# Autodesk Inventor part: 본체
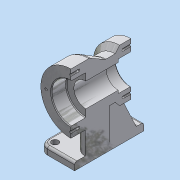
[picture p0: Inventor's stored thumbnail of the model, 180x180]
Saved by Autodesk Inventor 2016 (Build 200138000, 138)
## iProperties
Created: 2019-01
Part Number: 본체
Material: 알루미늄 6061
Document SubType Name: Modeling
Designer: Administrator
Density: 2.7 g/cm^3
Appearance: 알루미늄 - 평지
Mass: 897.041 g
Surface Area: 614.897 cm^2
Volume: 332.237 cm^3
Author: Administrator
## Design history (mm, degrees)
sketch "스케치1"
  geometry: L1 (46, -46)-(-46, -46); L2 (-46, -46)-(-46, 46); L3 (-46, 46)-(46, 46); L4 (46, 46)-(46, -46); L5 (46, -46)-(-46, 46); L6 (-46, -46)-(46, 46); 1 further point
  constraints: 12 end point, 2 midpoint, 2 parallel, 1 horizontal, 1 perpendicular
  dimensions: "d0" = 92 distance of L2.end L3.end; "d1" = 92 distance of L1.end L2.end
extrude "돌출1" new body sketch "스케치1" distance "d2" = 10; taper "d3" = 0 deg
fillet "모깎기1" dims "d4" = 10
sketch "스케치2"
  geometry: L1 (-46, 0)-(-51, 0); L2 (-51, 0)-(-51, 80); L3 (-86.37, 80)-(85.306, 80); L4 (-51, 80)-(-51, 120); L5 (-51, 120)-(-26, 120); L6 (-26, 120)-(-5.215, 108); L7 (-5.215, 108)-(8.126, 108); L8 (8.126, 108)-(14, 115); L9 (14, 115)-(29, 115); L10 (29, 115)-(29, 80); L11 (-51, 80)-(29, 80); 1 further point
  constraints: 22 end point, 3 perpendicular, 2 horizontal, 2 parallel, 1 collinear, 1 point on line, 1 vertical
  dimensions: "d5" = 5 distance of L1.start L1.end; "d6" = 80 distance of L1.end L2.end; "d7" = 40 distance of L2.end L4.end; "d8" = 25 distance of L4.end L5.end; "d9" = 30 deg angle of L7 L6; "d10" = 50 deg angle of L7 L8; "d11" = 15 distance of L8.end L9.end; "d12" = 80 horizontal distance of L9.end L4.end; "d13" = 70 diameter of L9 L3; "d14" = 56 diameter of L7 L3
revolve "회전1" sketch "스케치2" stored, may be unused: angle "d15" = 90 deg
sketch "스케치3"
  geometry: L1 (-51, 40)-(-51, 120) reference; L2 (-69.608, 80)-(66.232, 80); L3 (-51, 80)-(-51, 106); L4 (-51, 106)-(-31, 106); L5 (-31, 106)-(-31, 96); L6 (-31, 96)-(12, 96); L7 (12, 96)-(12, 100); L8 (12, 100)-(29, 100); L9 (29, 45)-(29, 115) reference; L10 (29, 100)-(29, 80); L11 (-51, 80)-(29, 80); 1 further point
  constraints: 18 end point, 5 perpendicular, 3 point on line, 2 horizontal, 2 midpoint
  dimensions: "d17" = 20 distance of L3.end L4.end; "d18" = 17 distance of L7.end L8.end; "d20" = 32 diameter of L6 L2; "d21" = 40 diameter of L8 L2; "d22" = 52 diameter of L4 L2
revolve "회전2" sketch "스케치3" stored, may be unused: angle "d23" = 90 deg
sketch "스케치5"
  geometry: L1 (-36, 46)-(36, 46) reference; L2 (46, 36)-(46, -36) reference; L3 (36, -46)-(-36, -46) reference; L4 (-46, -36)-(-46, 36) reference; C1 r 4.5 at (-36, 36); C2 r 4.5 at (36, 36); C3 r 4.5 at (-36, -36); C4 r 4.5 at (36, -36); A1 r 10 centre (-36, 36) between (-36, 46) and (-46, 36) reference; A2 r 10 centre (36, 36) between (46, 36) and (36, 46) reference; A3 r 10 centre (36, -36) between (36, -46) and (46, -36) reference; A4 r 10 centre (-36, -36) between (-46, -36) and (-36, -46) reference; 1 further point
  constraints: 4 centre point, 4 coincident
  dimensions: "d25" = 9 diameter of C1; "d26" = 9 diameter of C2; "d27" = 9 diameter of C3; "d28" = 9 diameter of C4
extrude "돌출2" cut sketch "스케치5" stored distance "d29" = 10; taper "d30" = 0 deg
sketch "스케치6"
  geometry: L1 (0, 72)-(0, 0) reference; L2 (-10, -10)-(0, -10) reference; 2 further points
  constraints: 1 other
  dimensions: "d31" = 4 distance from line of L1 point (-4, 36); "d32" = 46 distance from line of L2 point (-4, 36)
feature "엠보싱1" sketch "스케치6" dims "d0" = 92, "d1" = 92, "d33" = 0.5, "d34" = 0
fillet "모깎기2" dims "d35" = 3
sketch "스케치8" dims "d37" = 66
  geometry: L1 (0, 0)-(0, 33); C1 r 26 at (0, 0) reference; C2 r 40 at (0, 0) reference; C3 r 26 at (0, 0) reference; C4 r 16 at (0, 0) reference; 1 further point
  constraints: 2 end point, 1 coincident, 1 vertical, 1 vertical alignment, 2 other
hole "구멍1" sketch "스케치8" at (0, 33) diameter "d38" = 3.242; stored, may be unused: countersink angle "d42" = 82 deg, drill point angle "d44" = 118 deg; dims "d39" = 9, "d40" = 3.023, "d41" = 2, "d43" = 11
sketch "스케치9" dims "d48" = 55
  geometry: L1 (0, 0)-(0, -27.5); C1 r 35 at (0, 0) reference; 1 further point
  constraints: 2 end point, 1 coincident, 1 vertical, 1 vertical alignment, 2 other
hole "구멍2" sketch "스케치9" at (0, -27.5) diameter "d49" = 3.242; stored, may be unused: countersink angle "d53" = 82 deg, drill point angle "d55" = 118 deg; dims "d50" = 9, "d51" = 3.023, "d52" = 2, "d54" = 11
sketch "스케치11"
  geometry: L1 (36, -46)-(-36, -46) reference; L2 (0, -46)-(0, -16); L3 (0, -16)-(-46, -16); L4 (36, 46)-(-36, 46) reference; L5 (0, 46)-(0, 36); L6 (0, 36)-(-17.369, 36); L7 (0, 36)-(0, -8.49); C1 r 16 at (0, -16); 2 further points
  constraints: 12 end point, 3 midpoint, 3 vertical, 2 perpendicular, 1 centre point, 1 coincident
  dimensions: "d70" = 30 distance of L2.start L2.end; "d71" = 46 distance of L2.end L3.end; "d73" = 10 distance of L5.start L5.end; "d76" = 32 diameter of C1
extrude "돌출4" join sketch "스케치11" stored distance "d77" = 10; taper "d78" = 0 deg
sketch "스케치14"
  geometry: L1 (0, 10)-(0, 52) reference; L2 (-36, 10)-(36, 10) reference; L3 (0, 10)-(36, 10); L4 (36, 10)-(19.679, 45); L5 (14, 45)-(29, 45) reference; L6 (19.679, 45)-(14, 45); L7 (14, 45)-(8.126, 52); L8 (8.126, 52)-(14, 45) reference; L9 (8.126, 52)-(8.126, 108) reference; L10 (8.126, 52)-(0, 52); L11 (0, 52)-(8.126, 52) reference; L12 (0, 10)-(0, 52); 1 further point
  constraints: 12 end point, 4 point on line, 3 collinear
  dimensions: "d85" = 65 deg angle of L4 L3
extrude "돌출6" join sketch "스케치14" stored distance "d86" = 10; taper "d87" = 0 deg
chamfer "모따기1" distance "d88" = 1; stored, may be unused: second distance "d89" = 2, angle "d90" = 45 deg
feature "분할1"
chamfer "모따기3" distance "d94" = 1; stored, may be unused: second distance "d95" = 2, angle "d96" = 45 deg
fillet "모깎기3" dims "d97" = 3
fillet "모깎기4" dims "d98" = 3
feature "분할2"
node "솔리드1"
pattern_circular "원형 패턴1" dims angle "d46" = 360 deg
pattern_circular "원형 패턴2" dims angle "d57" = 360 deg
node "투영된 루프2"
node "투영된 루프4"
node "투영된 루프5"
